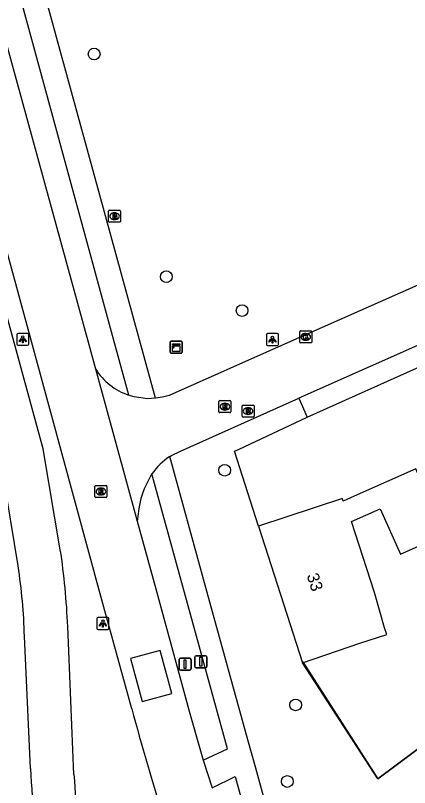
# Model space of a CAD drawing. Extents: x 156664 to 157568, y 383571 to 384421.
# Drawn here: x 157142.1 to 157175, y 383808.5 to 383872.9 of the extents above; entities that cross this region are included whole.
import ezdxf

# ---------------------------------------------------------------- set-up
doc = ezdxf.new("R2010")
doc.units = 0
for name, color, linetype in [('IMGEO_Afsluitpaal', 7, 'Continuous'), ('IMGEO_Boom', 7, 'Continuous'), ('IMGEO_Brandkraan', 7, 'Continuous'), ('IMGEO_Fietspad_gesloten', 7, 'Continuous'), ('IMGEO_Groenvoorziening', 7, 'Continuous'), ('IMGEO_Hek', 7, 'Continuous'), ('IMGEO_Kast', 7, 'Continuous'), ('IMGEO_Kolk', 7, 'Continuous'), ('IMGEO_Lichtpunt', 7, 'Continuous'), ('IMGEO_Pand', 7, 'Continuous'), ('IMGEO_Pand_nummerreeks', 7, 'Continuous'), ('IMGEO_Rijbaan_lokaal_open', 7, 'Continuous'), ('IMGEO_Rioolput', 7, 'Continuous'), ('IMGEO_Voetpad_open', 7, 'Continuous')]:
    doc.layers.add(name, color=color, linetype=linetype)

msp = doc.modelspace()

# ---------------------------------------------------------------- linework, layer by layer
at = {"layer": 'IMGEO_Afsluitpaal'}
for p, q in [((157155.788, 383818.392), (157155.788, 383819.192)), ((157155.788, 383819.192), (157155.788, 383818.392)), ((157155.888, 383819.292), (157156.678, 383819.292)), ((157156.678, 383819.292), (157155.888, 383819.292)), ((157156.778, 383819.192), (157156.778, 383818.392)), ((157156.778, 383818.392), (157156.778, 383819.192)), ((157157.1, 383818.596), (157157.1, 383819.396)), ((157157.1, 383819.396), (157157.1, 383818.596)), ((157157.2, 383819.496), (157157.99, 383819.496)), ((157157.99, 383819.496), (157157.2, 383819.496)), ((157158.09, 383819.396), (157158.09, 383818.596)), ((157158.09, 383818.596), (157158.09, 383819.396)), ((157157.99, 383818.496), (157157.2, 383818.496)), ((157157.2, 383818.496), (157157.99, 383818.496)), ((157156.678, 383818.292), (157155.888, 383818.292)), ((157155.888, 383818.292), (157156.678, 383818.292))]:
    msp.add_line(p, q, dxfattribs=at)
for points in [[(157156.208, 383819.167), (157156.358, 383819.167), (157156.358, 383818.417), (157156.208, 383818.417), (157156.208, 383819.167)], [(157157.52, 383819.371), (157157.67, 383819.371), (157157.67, 383818.621), (157157.52, 383818.621), (157157.52, 383819.371)]]:
    msp.add_lwpolyline(points, dxfattribs=at)
for centre, start, end in [((157155.888, 383819.192), 90, 180), ((157155.888, 383819.192), 90, 180), ((157156.678, 383819.192), 0, 90), ((157156.678, 383819.192), 360, 90), ((157157.2, 383819.396), 90, 180), ((157157.2, 383819.396), 90, 180), ((157157.99, 383819.396), 0, 90), ((157157.99, 383819.396), 360, 90), ((157157.2, 383818.596), 180, 270), ((157157.2, 383818.596), 180, 270), ((157157.99, 383818.596), 270, 0), ((157157.99, 383818.596), 270, 0), ((157155.888, 383818.392), 180, 270), ((157155.888, 383818.392), 180, 270), ((157156.678, 383818.392), 270, 0), ((157156.678, 383818.392), 270, 0)]:
    msp.add_arc(centre, 0.1, start, end, dxfattribs=at)
at = {"layer": 'IMGEO_Boom'}
for centre in [(157148.701, 383869.681), (157154.721, 383851.109), (157161.041, 383848.284), (157159.587, 383834.97), (157165.502, 383815.396), (157164.807, 383809.008)]:
    msp.add_circle(centre, 0.489, dxfattribs=at)
at = {"layer": 'IMGEO_Brandkraan'}
for p, q in [((157149.905, 383855.726), (157149.905, 383856.578)), ((157149.98, 383856.652), (157150.832, 383856.652)), ((157150.906, 383856.578), (157150.906, 383855.726)), ((157150.416, 383855.872), (157150.391, 383855.872)), ((157150.393, 383856.432), (157150.418, 383856.432)), ((157150.832, 383855.652), (157149.98, 383855.652))]:
    msp.add_line(p, q, dxfattribs=at)
for points in [[(157149.905, 383855.726), (157149.905, 383856.578)], [(157149.98, 383856.652), (157150.832, 383856.652)], [(157150.906, 383856.578), (157150.906, 383855.726)], [(157150.253, 383856.352), (157150.253, 383855.952), (157150.466, 383855.952)], [(157150.484, 383856.352), (157150.253, 383856.352)], [(157150.432, 383856.271), (157150.378, 383856.271), (157150.378, 383856.195)], [(157150.378, 383856.195), (157150.431, 383856.195)], [(157150.44, 383856.119), (157150.378, 383856.119), (157150.378, 383856.038)], [(157150.378, 383856.038), (157150.44, 383856.038)], [(157150.832, 383855.652), (157149.98, 383855.652)]]:
    msp.add_lwpolyline(points, dxfattribs=at)
for centre, radius, start, end in [((157149.982, 383856.576), 0.0765, 91.55205, 178.44795), ((157149.982, 383856.576), 0.0765, 91.55205, 178.44795), ((157150.83, 383856.576), 0.0765, 1.55205, 88.44795), ((157150.83, 383856.576), 0.0765, 1.55205, 88.44795), ((157150.433, 383856.233), 0.0379, 267.82845, 90.93552), ((157150.441, 383856.078), 0.0404, 269.87594, 90.50774), ((157150.472, 383856.203), 0.251, 268.66757, 293.53466), ((157150.488, 383856.207), 0.145, 59.4692, 91.53667), ((157150.513, 383856.254), 0.0922, 285.51372, 58.15012), ((157150.518, 383856.062), 0.105, 301.31148, 78.98903), ((157149.982, 383855.728), 0.0765, 181.55205, 268.44795), ((157149.982, 383855.728), 0.0765, 181.55205, 268.44795), ((157150.83, 383855.728), 0.0765, 271.55205, 358.44795), ((157150.83, 383855.728), 0.0765, 271.55205, 358.44795)]:
    msp.add_arc(centre, radius, start, end, dxfattribs=at)
for centre, major_axis, ratio, start_param, end_param in [((157150.392, 383856.152), (-0.387, 0.002), 0.722429, 4.712389, 7.853982), ((157150.417, 383856.152), (-0.39, 0.002), 0.717154, 1.570796, 4.712389)]:
    msp.add_ellipse(centre, major_axis=major_axis, ratio=ratio, start_param=start_param, end_param=end_param, dxfattribs=at)
at = {"layer": 'IMGEO_Fietspad_gesloten'}
for points in [[(157145.881, 383828.34), (157144.437, 383836.755), (157141.79, 383846.532), (157125.103, 383907.619)], [(157142.354, 383826.982), (157141.11, 383834.602)], [(157147.02, 383809.594), (157146.503, 383821.933)], [(157143.395, 383810.081), (157142.887, 383821.12)]]:
    msp.add_lwpolyline(points, dxfattribs=at)
for centre, radius, start, end in [((157085.172, 383819.213), 61.391, 2.53973, 8.55021), ((157098.62, 383820.05), 44.28, 1.38434, 9.00628), ((157255.501, 383816.08), 112.266, 183.06285, 187.73834), ((157239.456, 383814.645), 92.574, 183.12772, 188.36091)]:
    msp.add_arc(centre, radius, start, end, dxfattribs=at)
at = {"layer": 'IMGEO_Groenvoorziening'}
for points in [[(157162.399, 383830.305), (157160.414, 383836.55), (157160.744, 383836.697), (157166.456, 383839.4)], [(157197.76, 383829.022), (157198.498, 383827.273), (157178.373, 383813.716), (157172.345, 383809.218), (157166.087, 383818.909)]]:
    msp.add_lwpolyline(points, dxfattribs=at)
at = {"layer": 'IMGEO_Hek'}
msp.add_lwpolyline([(157166.095, 383818.977), (157172.345, 383809.218), (157178.373, 383813.716), (157198.498, 383827.273), (157197.76, 383829.022)], dxfattribs=at)
at = {"layer": 'IMGEO_Kast'}
for p, q in [((157155.045, 383844.808), (157155.045, 383845.649)), ((157155.045, 383845.649), (157155.045, 383844.808)), ((157155.12, 383845.733), (157155.961, 383845.733)), ((157155.961, 383845.733), (157155.12, 383845.733)), ((157156.045, 383845.658), (157156.045, 383844.817)), ((157156.045, 383844.817), (157156.045, 383845.658)), ((157155.97, 383844.733), (157155.129, 383844.733)), ((157155.129, 383844.733), (157155.97, 383844.733))]:
    msp.add_line(p, q, dxfattribs=at)
for points in [[(157155.24, 383845.523), (157155.84, 383845.523), (157155.84, 383845.438), (157155.24, 383845.438), (157155.24, 383845.523)], [(157155.24, 383845.348), (157155.84, 383845.348), (157155.84, 383844.859), (157155.24, 383844.859), (157155.24, 383845.348)]]:
    msp.add_lwpolyline(points, dxfattribs=at)
msp.add_circle((157155.324, 383845.197), 0.0377, dxfattribs=at)
for centre, start, end in [((157155.123, 383845.655), 92.4484, 184.28452), ((157155.123, 383845.655), 92.4484, 184.28452), ((157155.967, 383845.655), 2.4484, 94.28452), ((157155.967, 383845.655), 2.4484, 94.28452), ((157155.123, 383844.811), 182.4484, 274.28452), ((157155.123, 383844.811), 182.4484, 274.28452), ((157155.967, 383844.811), 272.4484, 4.28452), ((157155.967, 383844.811), 272.4484, 4.28452)]:
    msp.add_arc(centre, 0.0779, start, end, dxfattribs=at)
at = {"layer": 'IMGEO_Kolk'}
for p, q in [((157165.843, 383845.661), (157165.843, 383846.513)), ((157165.918, 383846.587), (157166.77, 383846.587)), ((157166.331, 383846.367), (157166.356, 383846.367)), ((157166.844, 383846.513), (157166.844, 383845.661)), ((157166.77, 383845.587), (157165.918, 383845.587)), ((157166.354, 383845.807), (157166.329, 383845.807))]:
    msp.add_line(p, q, dxfattribs=at)
for points in [[(157165.843, 383845.661), (157165.843, 383846.513)], [(157165.918, 383846.587), (157166.77, 383846.587)], [(157166.164, 383846.287), (157166.287, 383846.287), (157166.287, 383846.136), (157166.417, 383846.287), (157166.581, 383846.287), (157166.435, 383846.136), (157166.588, 383845.887), (157166.436, 383845.887), (157166.351, 383846.051), (157166.287, 383845.984), (157166.287, 383845.887), (157166.164, 383845.887), (157166.164, 383846.287)], [(157166.844, 383846.513), (157166.844, 383845.661)], [(157166.77, 383845.587), (157165.918, 383845.587)]]:
    msp.add_lwpolyline(points, dxfattribs=at)
for centre, start, end in [((157165.92, 383846.511), 91.55205, 178.44795), ((157165.92, 383846.511), 91.55205, 178.44795), ((157166.768, 383846.511), 1.55205, 88.44795), ((157166.768, 383846.511), 1.55205, 88.44795), ((157165.92, 383845.663), 181.55205, 268.44795), ((157165.92, 383845.663), 181.55205, 268.44795), ((157166.768, 383845.663), 271.55205, 358.44795), ((157166.768, 383845.663), 271.55205, 358.44795)]:
    msp.add_arc(centre, 0.0765, start, end, dxfattribs=at)
for centre, major_axis, ratio, start_param, end_param in [((157166.33, 383846.087), (-0.387, 0.002), 0.722429, 4.712389, 7.853982), ((157166.355, 383846.087), (-0.39, 0.002), 0.717154, 1.570796, 4.712389)]:
    msp.add_ellipse(centre, major_axis=major_axis, ratio=ratio, start_param=start_param, end_param=end_param, dxfattribs=at)
at = {"layer": 'IMGEO_Lichtpunt'}
for p, q in [((157142.252, 383846.29), (157142.252, 383845.483)), ((157142.252, 383846.29), (157142.252, 383845.483)), ((157143.154, 383846.385), (157142.346, 383846.385)), ((157143.154, 383846.385), (157142.346, 383846.385)), ((157143.248, 383845.483), (157143.248, 383846.29)), ((157143.248, 383845.483), (157143.248, 383846.29)), ((157163.073, 383846.263), (157163.073, 383845.456)), ((157163.073, 383846.263), (157163.073, 383845.456)), ((157163.975, 383846.358), (157163.167, 383846.358)), ((157163.975, 383846.358), (157163.167, 383846.358)), ((157164.069, 383845.456), (157164.069, 383846.263)), ((157164.069, 383845.456), (157164.069, 383846.263)), ((157142.346, 383845.389), (157143.154, 383845.389)), ((157142.346, 383845.389), (157143.154, 383845.389)), ((157163.167, 383845.362), (157163.975, 383845.362)), ((157163.167, 383845.362), (157163.975, 383845.362)), ((157148.929, 383822.59), (157148.929, 383821.783)), ((157148.929, 383822.59), (157148.929, 383821.783)), ((157149.831, 383822.685), (157149.023, 383822.685)), ((157149.831, 383822.685), (157149.023, 383822.685)), ((157149.925, 383821.783), (157149.925, 383822.59)), ((157149.925, 383821.783), (157149.925, 383822.59)), ((157149.023, 383821.689), (157149.831, 383821.689)), ((157149.023, 383821.689), (157149.831, 383821.689))]:
    msp.add_line(p, q, dxfattribs=at)
for points in [[(157142.626, 383845.954), (157142.665, 383845.926), (157142.477, 383845.664), (157142.439, 383845.691), (157142.626, 383845.954)], [(157142.728, 383845.906), (157142.775, 383845.906), (157142.775, 383845.584), (157142.728, 383845.584), (157142.728, 383845.906)], [(157142.838, 383845.926), (157142.876, 383845.953), (157143.063, 383845.691), (157143.024, 383845.663), (157142.838, 383845.926)], [(157163.447, 383845.927), (157163.486, 383845.899), (157163.298, 383845.637), (157163.26, 383845.664), (157163.447, 383845.927)], [(157163.549, 383845.879), (157163.596, 383845.879), (157163.596, 383845.557), (157163.549, 383845.557), (157163.549, 383845.879)], [(157163.659, 383845.899), (157163.697, 383845.926), (157163.884, 383845.664), (157163.845, 383845.636), (157163.659, 383845.899)], [(157149.303, 383822.254), (157149.342, 383822.226), (157149.154, 383821.964), (157149.116, 383821.991), (157149.303, 383822.254)], [(157149.405, 383822.206), (157149.452, 383822.206), (157149.452, 383821.884), (157149.405, 383821.884), (157149.405, 383822.206)], [(157149.515, 383822.226), (157149.553, 383822.253), (157149.74, 383821.991), (157149.701, 383821.963), (157149.515, 383822.226)]]:
    msp.add_lwpolyline(points, dxfattribs=at)
for centre in [(157142.751, 383846.088), (157163.572, 383846.061), (157149.428, 383822.388)]:
    msp.add_circle(centre, 0.0994, dxfattribs=at)
for centre, start, end in [((157142.346, 383846.29), 90, 180), ((157142.346, 383846.29), 90, 180), ((157143.154, 383846.29), 0, 90), ((157143.154, 383846.29), 0, 90), ((157163.167, 383846.263), 90, 180), ((157163.167, 383846.263), 90, 180), ((157163.975, 383846.263), 0, 90), ((157163.975, 383846.263), 0, 90), ((157142.346, 383845.483), 180, 270), ((157142.346, 383845.483), 180, 270), ((157143.154, 383845.483), 270, 0), ((157143.154, 383845.483), 270, 360), ((157163.167, 383845.456), 180, 270), ((157163.167, 383845.456), 180, 270), ((157163.975, 383845.456), 270, 0), ((157163.975, 383845.456), 270, 360), ((157149.023, 383822.59), 90, 180), ((157149.023, 383822.59), 90, 180), ((157149.831, 383822.59), 0, 90), ((157149.831, 383822.59), 0, 90), ((157149.023, 383821.783), 180, 270), ((157149.023, 383821.783), 180, 270), ((157149.831, 383821.783), 270, 0), ((157149.831, 383821.783), 270, 360)]:
    msp.add_arc(centre, 0.0946, start, end, dxfattribs=at)
at = {"layer": 'IMGEO_Pand'}
for points in [[(157166.087, 383818.909), (157170.847, 383820.534), (157173.099, 383821.272), (157172.919, 383821.821), (157172.08, 383824.782), (157170.169, 383830.692), (157172.557, 383831.756), (157174.246, 383827.965), (157177.927, 383829.605), (157175.515, 383835.08), (157170.373, 383832.791), (157169.459, 383832.385), (157169.407, 383832.596), (157162.399, 383830.305)], [(157162.399, 383830.305), (157166.087, 383818.909)]]:
    msp.add_lwpolyline(points, dxfattribs=at)
at = {"layer": 'IMGEO_Rijbaan_lokaal_open'}
for points in [[(157129.083, 383915.456), (157137.15, 383886.135), (157141.176, 383871.297), (157148.817, 383843.411)], [(157151.838, 383815.069), (157149.3, 383824.346), (157125.795, 383910.624), (157125.737, 383910.814)], [(157200.633, 383861.445), (157164.329, 383845.363), (157154.951, 383841.199), (157154.389, 383841.05), (157153.812, 383840.967)], [(157209.005, 383860.154), (157203.743, 383857.815), (157195.261, 383854.066), (157165.775, 383840.978)], [(157148.817, 383843.411), (157152.292, 383830.729)], [(157153.812, 383840.967), (157153.156, 383840.918), (157152.032, 383841.081), (157151.722, 383841.182), (157151.588, 383841.225)], [(157155.023, 383836.109), (157155.154, 383836.189), (157155.906, 383836.57), (157165.775, 383840.978)], [(157153.519, 383834.655), (157153.465, 383834.573)], [(157152.367, 383831.338), (157152.292, 383830.729)], [(157152.292, 383830.729), (157153.841, 383825.076), (157156.682, 383814.685), (157157.801, 383810.799)], [(157152.707, 383815.673), (157155.174, 383816.336), (157154.205, 383819.941), (157151.738, 383819.278), (157152.707, 383815.673)], [(157157.801, 383810.799), (157158.529, 383808.484)]]:
    msp.add_lwpolyline(points, dxfattribs=at)
for centre, radius, start, end in [((157153.344, 383846.3), 5.37, 212.54559, 250.91566), ((157157.716, 383831.818), 5.066, 122.11553, 145.94767), ((157159.87, 383830.595), 7.539, 148.15757, 174.34671), ((157352.266, 383868.656), 207.468, 194.96853, 200.19449)]:
    msp.add_arc(centre, radius, start, end, dxfattribs=at)
at = {"layer": 'IMGEO_Rioolput'}
for p, q in [((157159.102, 383839.844), (157159.102, 383840.696)), ((157159.177, 383840.77), (157160.029, 383840.77)), ((157159.59, 383840.55), (157159.615, 383840.55)), ((157160.103, 383840.696), (157160.103, 383839.844)), ((157161.114, 383840.401), (157161.966, 383840.401)), ((157160.029, 383839.77), (157159.177, 383839.77)), ((157159.613, 383839.99), (157159.588, 383839.99)), ((157161.039, 383839.475), (157161.039, 383840.327)), ((157161.527, 383840.181), (157161.552, 383840.181)), ((157162.04, 383840.327), (157162.04, 383839.475)), ((157161.966, 383839.401), (157161.114, 383839.401)), ((157161.55, 383839.621), (157161.525, 383839.621)), ((157148.766, 383832.763), (157148.766, 383833.615)), ((157148.841, 383833.689), (157149.693, 383833.689)), ((157149.254, 383833.469), (157149.279, 383833.469)), ((157149.767, 383833.615), (157149.767, 383832.763)), ((157149.693, 383832.689), (157148.841, 383832.689)), ((157149.277, 383832.909), (157149.252, 383832.909))]:
    msp.add_line(p, q, dxfattribs=at)
for points in [[(157159.102, 383839.844), (157159.102, 383840.696)], [(157159.177, 383840.77), (157160.029, 383840.77)], [(157159.691, 383840.468), (157159.439, 383840.47), (157159.439, 383840.07)], [(157159.617, 383840.389), (157159.563, 383840.389), (157159.563, 383840.308)], [(157160.103, 383840.696), (157160.103, 383839.844)], [(157161.114, 383840.401), (157161.966, 383840.401)], [(157160.029, 383839.77), (157159.177, 383839.77)], [(157159.439, 383840.07), (157159.563, 383840.07), (157159.563, 383840.232), (157159.574, 383840.232)], [(157159.563, 383840.308), (157159.615, 383840.308)], [(157159.621, 383840.203), (157159.692, 383840.07), (157159.832, 383840.07), (157159.767, 383840.196)], [(157161.039, 383839.475), (157161.039, 383840.327)], [(157161.628, 383840.099), (157161.376, 383840.101), (157161.376, 383839.701)], [(157161.376, 383839.701), (157161.5, 383839.701), (157161.5, 383839.863), (157161.511, 383839.863)], [(157161.554, 383840.02), (157161.5, 383840.02), (157161.5, 383839.939)], [(157161.5, 383839.939), (157161.552, 383839.939)], [(157161.558, 383839.834), (157161.629, 383839.701), (157161.769, 383839.701), (157161.704, 383839.827)], [(157162.04, 383840.327), (157162.04, 383839.475)], [(157161.966, 383839.401), (157161.114, 383839.401)], [(157148.766, 383832.763), (157148.766, 383833.615)], [(157148.841, 383833.689), (157149.693, 383833.689)], [(157149.355, 383833.387), (157149.103, 383833.389), (157149.103, 383832.989)], [(157149.281, 383833.308), (157149.227, 383833.308), (157149.227, 383833.227)], [(157149.767, 383833.615), (157149.767, 383832.763)], [(157149.693, 383832.689), (157148.841, 383832.689)], [(157149.103, 383832.989), (157149.227, 383832.989), (157149.227, 383833.151), (157149.238, 383833.151)], [(157149.227, 383833.227), (157149.279, 383833.227)], [(157149.285, 383833.122), (157149.356, 383832.989), (157149.496, 383832.989), (157149.431, 383833.115)]]:
    msp.add_lwpolyline(points, dxfattribs=at)
for centre, radius, start, end in [((157159.179, 383840.694), 0.0765, 91.55205, 178.44795), ((157159.179, 383840.694), 0.0765, 91.55205, 178.44795), ((157159.623, 383840.293), 0.0964, 77.00612, 93.18647), ((157159.637, 383840.35), 0.0378, 276.66336, 79.67722), ((157159.69, 383840.358), 0.109, 350.36119, 89.41601), ((157160.027, 383840.694), 0.0765, 1.55205, 88.44795), ((157160.027, 383840.694), 0.0765, 1.55205, 88.44795), ((157161.116, 383840.325), 0.0765, 91.55205, 178.44795), ((157161.116, 383840.325), 0.0765, 91.55205, 178.44795), ((157161.964, 383840.325), 0.0765, 1.55205, 88.44795), ((157161.964, 383840.325), 0.0765, 1.55205, 88.44795), ((157159.179, 383839.846), 0.0765, 181.55205, 268.44795), ((157159.179, 383839.846), 0.0765, 181.55205, 268.44795), ((157159.573, 383840.179), 0.0533, 26.02933, 88.69889), ((157159.599, 383840.497), 0.19, 274.7715, 282.96867), ((157159.688, 383840.358), 0.112, 277.58423, 350.98172), ((157159.672, 383840.143), 0.108, 29.51342, 73.79051), ((157160.027, 383839.846), 0.0765, 271.55205, 358.44795), ((157160.027, 383839.846), 0.0765, 271.55205, 358.44795), ((157161.51, 383839.81), 0.0533, 26.02933, 88.69889), ((157161.536, 383840.128), 0.19, 274.7715, 282.96867), ((157161.56, 383839.924), 0.0964, 77.00612, 93.18647), ((157161.574, 383839.981), 0.0378, 276.66336, 79.67722), ((157161.627, 383839.989), 0.109, 350.36119, 89.41601), ((157161.625, 383839.989), 0.112, 277.58423, 350.98172), ((157161.609, 383839.774), 0.108, 29.51342, 73.79051), ((157161.116, 383839.477), 0.0765, 181.55205, 268.44795), ((157161.116, 383839.477), 0.0765, 181.55205, 268.44795), ((157161.964, 383839.477), 0.0765, 271.55205, 358.44795), ((157161.964, 383839.477), 0.0765, 271.55205, 358.44795), ((157148.843, 383833.613), 0.0765, 91.55205, 178.44795), ((157148.843, 383833.613), 0.0765, 91.55205, 178.44795), ((157149.287, 383833.212), 0.0964, 77.00612, 93.18647), ((157149.301, 383833.269), 0.0378, 276.66336, 79.67722), ((157149.354, 383833.277), 0.109, 350.36119, 89.41601), ((157149.691, 383833.613), 0.0765, 1.55205, 88.44795), ((157149.691, 383833.613), 0.0765, 1.55205, 88.44795), ((157148.843, 383832.765), 0.0765, 181.55205, 268.44795), ((157148.843, 383832.765), 0.0765, 181.55205, 268.44795), ((157149.237, 383833.098), 0.0533, 26.02933, 88.69889), ((157149.263, 383833.416), 0.19, 274.7715, 282.96867), ((157149.352, 383833.277), 0.112, 277.58423, 350.98172), ((157149.336, 383833.062), 0.108, 29.51342, 73.79051), ((157149.691, 383832.765), 0.0765, 271.55205, 358.44795), ((157149.691, 383832.765), 0.0765, 271.55205, 358.44795)]:
    msp.add_arc(centre, radius, start, end, dxfattribs=at)
for centre, major_axis, ratio, start_param, end_param in [((157159.589, 383840.27), (-0.387, 0.002), 0.722429, 4.712389, 7.853982), ((157159.614, 383840.27), (-0.39, 0.002), 0.717154, 1.570796, 4.712389), ((157161.526, 383839.901), (-0.387, 0.002), 0.722429, 4.712389, 7.853982), ((157161.551, 383839.901), (-0.39, 0.002), 0.717154, 1.570796, 4.712389), ((157149.253, 383833.189), (-0.387, 0.002), 0.722429, 4.712389, 7.853982), ((157149.278, 383833.189), (-0.39, 0.002), 0.717154, 1.570796, 4.712389)]:
    msp.add_ellipse(centre, major_axis=major_axis, ratio=ratio, start_param=start_param, end_param=end_param, dxfattribs=at)
at = {"layer": 'IMGEO_Voetpad_open'}
for points in [[(157151.588, 383841.225), (157150.233, 383846.197), (157138.346, 383889.799), (157132.538, 383911.039), (157132.306, 383911.778), (157131.455, 383914.488)], [(157153.812, 383840.967), (157140.251, 383890.375), (157136.032, 383905.936)], [(157166.456, 383839.4), (157196.244, 383852.736), (157199.451, 383854.14)], [(157165.775, 383840.978), (157166.456, 383839.4)], [(157164.196, 383802.809), (157162.178, 383810.117), (157161.525, 383812.481), (157158.13, 383824.776), (157155.023, 383836.109)], [(157157.801, 383810.799), (157159.831, 383811.735), (157153.519, 383834.655)], [(157158.529, 383808.484), (157160.463, 383809.429), (157162.079, 383803.555)]]:
    msp.add_lwpolyline(points, dxfattribs=at)

# ---------------------------------------------------------------- texts
at = {"layer": 'IMGEO_Pand_nummerreeks'}
msp.add_text('33', height=1, rotation=287.91618, dxfattribs=at).set_placement((157166.411, 383826.194))

doc.saveas('drawing.dxf')
